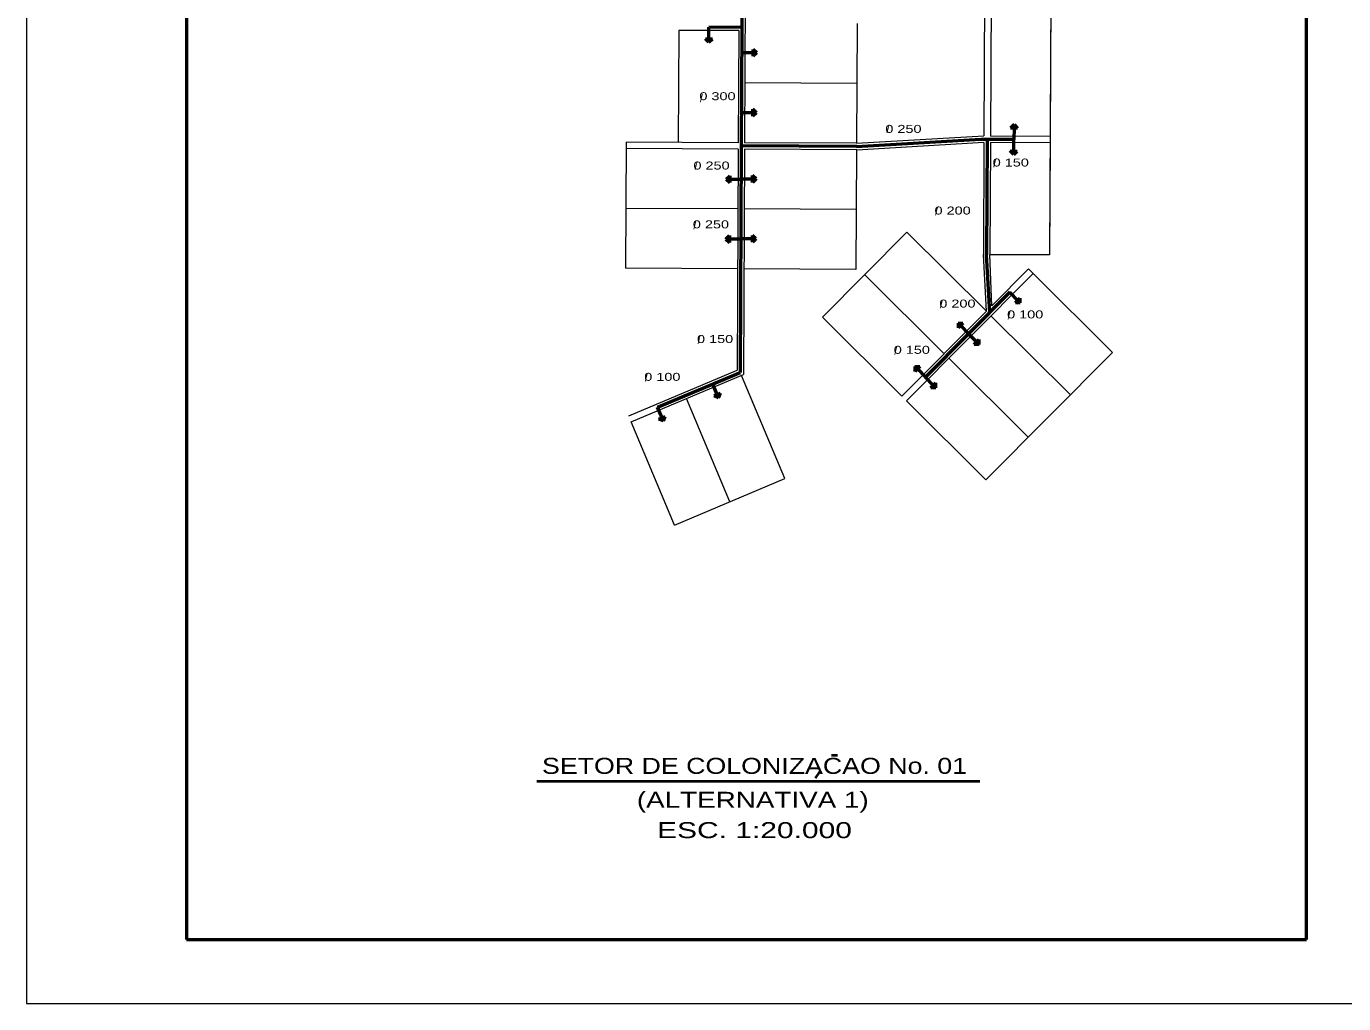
# Model space of a CAD drawing. Extents: x 312964 to 351929, y 9004151 to 9034973.
# Drawn here: x 343351 to 347467, y 9013061 to 9016114 of the extents above; entities that cross this region are included whole.
import ezdxf
from ezdxf.enums import TextEntityAlignment as Align

# ---------------------------------------------------------------- set-up
doc = ezdxf.new("R2010")
doc.units = 0
doc.header["$LTSCALE"] = 10
doc.layers.add('1', color=7, linetype='Continuous', lineweight=13)
doc.layers.add('2', color=7, linetype='Continuous', lineweight=53)

msp = doc.modelspace()

# ---------------------------------------------------------------- linework, layer by layer
at = {"layer": '1', "lineweight": 53}
for p, q in [((343850.92, 9018801.07), (343850.92, 9013261.07)), ((347350.92, 9013261.07), (347350.92, 9018801.07)), ((343850.92, 9013261.07), (347350.92, 9013261.07))]:
    msp.add_line(p, q, dxfattribs=at)
at = {"layer": '1', "lineweight": 40}
for p, q in [((345866.77, 9013837.69), (345885.06, 9013837.69)), ((344945.51, 9013756.03), (346329.85, 9013756.03)), ((345828.79, 9013785.6), (345816.12, 9013765.89))]:
    msp.add_line(p, q, dxfattribs=at)
at = {"layer": '1'}
msp.add_lwpolyline([(343350.92, 9019001.07), (343350.92, 9013061.07), (347550.92, 9013061.07), (347550.92, 9019001.07)], close=True, dxfattribs=at)
at = {"layer": '2', "lineweight": 13}
for p, q in [((345598.53, 9016474.5), (345594.98, 9015750.51)), ((346346.52, 9016470.83), (346343.09, 9015772.11)), ((346366.52, 9016470.73), (346363.09, 9015770.74)), ((346553.51, 9016469.82), (346548.27, 9015399.83)), ((346553.51, 9016469.82), (346550.08, 9015769.83)), ((345389.69, 9016101.52), (345387.98, 9015751.52)), ((345576.69, 9016100.6), (345389.69, 9016101.52)), ((345576.69, 9016100.6), (345574.98, 9015750.61)), ((345946.81, 9016122.79), (345944.97, 9015748.79)), ((345945.89, 9015935.79), (345595.89, 9015937.51)), ((345944.97, 9015748.79), (346343.09, 9015772.11)), ((346550.08, 9015769.83), (346363.09, 9015770.74)), ((345224.98, 9015752.32), (345223.05, 9015358.33)), ((345574.88, 9015730.61), (345224.88, 9015732.32)), ((345574.98, 9015750.61), (345224.98, 9015752.32)), ((345574.88, 9015730.61), (345571.49, 9015039.53)), ((345594.88, 9015730.51), (345591.43, 9015026.21)), ((345945.51, 9015728.79), (345594.88, 9015730.51)), ((345944.97, 9015748.79), (345594.98, 9015750.51)), ((345944.87, 9015728.79), (345943.04, 9015354.8)), ((345945.51, 9015728.79), (346342.99, 9015752.07)), ((346342.99, 9015750.8), (346341.27, 9015400.85)), ((346362.99, 9015750.74), (346361.27, 9015400.75)), ((346549.99, 9015749.83), (346362.99, 9015750.74)), ((346549.99, 9015749.83), (346548.27, 9015399.83)), ((345573.96, 9015543.61), (345223.97, 9015545.32)), ((345943.96, 9015541.79), (345593.96, 9015543.51)), ((346102.48, 9015470.74), (345838.75, 9015205.56)), ((346350.65, 9015223.93), (346102.48, 9015470.74)), ((346350.65, 9015223.93), (346341.27, 9015400.85)), ((346548.27, 9015399.83), (346361.27, 9015400.75)), ((346367.78, 9015241.15), (346361.27, 9015400.75)), ((345573.05, 9015356.61), (345223.05, 9015358.33)), ((345943.04, 9015354.8), (345593.05, 9015356.51)), ((346218.79, 9015091.34), (345970.62, 9015338.15)), ((346496.7, 9015342.42), (346101.1, 9014944.65)), ((346482.52, 9015356.53), (346367.78, 9015241.15)), ((346482.52, 9015356.53), (346496.7, 9015342.42)), ((346496.7, 9015342.42), (346744.86, 9015095.62)), ((346086.92, 9014958.75), (345838.75, 9015205.56)), ((346350.65, 9015223.93), (346086.92, 9014958.75)), ((346364.83, 9015209.83), (346613, 9014963.03)), ((346232.97, 9015077.24), (346481.13, 9014830.43)), ((346744.86, 9015095.62), (346349.27, 9014697.84)), ((345233.21, 9014897.37), (345571.49, 9015039.53)), ((345240.96, 9014878.94), (345591.43, 9015026.21)), ((345721.35, 9014701.16), (345585.75, 9015023.83)), ((345548.95, 9014628.72), (345413.35, 9014951.38)), ((346101.1, 9014944.65), (346349.27, 9014697.84)), ((345376.55, 9014556.27), (345240.96, 9014878.94)), ((345376.55, 9014556.27), (345721.35, 9014701.16))]:
    msp.add_line(p, q, dxfattribs=at)
at = {"layer": '2'}
for p, q in [((345586.74, 9016110.55), (345483.24, 9016111.06)), ((345483.29, 9016075.21), (345483.24, 9016111.06)), ((345472.77, 9016075.2), (345494.33, 9016075.23)), ((345483.56, 9016064.43), (345472.77, 9016075.2)), ((345483.56, 9016064.43), (345494.33, 9016075.23)), ((345622.2, 9016031.1), (345586.35, 9016031.05)), ((345622.21, 9016020.58), (345622.19, 9016042.14)), ((345632.98, 9016031.37), (345622.19, 9016042.14)), ((345632.98, 9016031.37), (345622.21, 9016020.58)), ((345621.3, 9015833.58), (345621.27, 9015855.14)), ((345632.06, 9015844.38), (345621.27, 9015855.14)), ((345621.28, 9015844.1), (345585.44, 9015844.06)), ((345632.06, 9015844.38), (345621.3, 9015833.58)), ((346437.1, 9015807.01), (346426.13, 9015796.42)), ((346447.69, 9015796.04), (346426.13, 9015796.42)), ((346437.17, 9015796.23), (346436.54, 9015760.38)), ((346437.1, 9015807.01), (346447.69, 9015796.04)), ((345945.56, 9015738.79), (345584.93, 9015740.56)), ((345944.92, 9015738.77), (346333.04, 9015761.5)), ((346436.54, 9015760.38), (346333.04, 9015760.89)), ((346353.04, 9015761.41), (346351.27, 9015400.8)), ((346435.9, 9015724.54), (346436.54, 9015760.38)), ((346425.38, 9015724.73), (346446.94, 9015724.34)), ((346435.97, 9015713.76), (346425.38, 9015724.73)), ((346435.97, 9015713.76), (346446.94, 9015724.34)), ((345537.79, 9015636.74), (345548.56, 9015647.53)), ((345548.56, 9015647.53), (345548.59, 9015625.97)), ((345620.28, 9015626.59), (345620.25, 9015648.14)), ((345631.05, 9015637.38), (345620.25, 9015648.14)), ((345537.79, 9015636.74), (345548.59, 9015625.97)), ((345548.57, 9015637.01), (345584.42, 9015637.06)), ((345620.27, 9015637.11), (345584.42, 9015637.06)), ((345631.05, 9015637.38), (345620.28, 9015626.59)), ((345536.88, 9015449.74), (345547.64, 9015460.53)), ((345536.88, 9015449.74), (345547.67, 9015438.97)), ((345547.64, 9015460.53), (345547.67, 9015438.97)), ((345547.66, 9015450.01), (345583.5, 9015450.06)), ((345619.35, 9015450.11), (345583.5, 9015450.06)), ((345619.37, 9015439.59), (345619.34, 9015461.15)), ((345630.13, 9015450.38), (345619.34, 9015461.15)), ((345630.13, 9015450.38), (345619.37, 9015439.59)), ((346361.36, 9015220.52), (346351.27, 9015400.8)), ((346423.67, 9015283.18), (346159.94, 9015017.99)), ((346448.64, 9015257.45), (346423.67, 9015283.18)), ((346441.09, 9015250.13), (346456.56, 9015265.14)), ((346456.33, 9015249.9), (346441.09, 9015250.13)), ((346456.33, 9015249.9), (346456.56, 9015265.14)), ((346262.29, 9015187.02), (346262.06, 9015171.78)), ((346277.53, 9015186.79), (346262.06, 9015171.78)), ((346262.29, 9015187.02), (346277.53, 9015186.79)), ((346269.98, 9015179.47), (346294.95, 9015153.74)), ((346319.91, 9015128.02), (346294.95, 9015153.74)), ((346312.36, 9015120.69), (346327.84, 9015135.71)), ((346327.61, 9015120.46), (346312.36, 9015120.69)), ((346327.61, 9015120.46), (346327.84, 9015135.71)), ((345323.28, 9014924.38), (345581.46, 9015032.87)), ((346127.28, 9015051.27), (346127.06, 9015036.03)), ((346142.53, 9015051.05), (346127.06, 9015036.03)), ((346127.28, 9015051.27), (346142.53, 9015051.05)), ((346134.98, 9015043.72), (346159.94, 9015017.99)), ((345509.54, 9014963.77), (345495.61, 9014996.8)), ((346184.91, 9014992.27), (346159.94, 9015017.99)), ((346177.36, 9014984.94), (346192.83, 9014999.96)), ((346192.6, 9014984.71), (346192.83, 9014999.96)), ((345499.85, 9014959.68), (345519.71, 9014968.06)), ((345513.97, 9014953.93), (345499.85, 9014959.68)), ((345513.97, 9014953.93), (345519.71, 9014968.06)), ((346192.6, 9014984.71), (346177.36, 9014984.94)), ((345337.21, 9014891.35), (345323.28, 9014924.38)), ((345327.52, 9014887.26), (345347.38, 9014895.64)), ((345341.64, 9014881.52), (345327.52, 9014887.26)), ((345341.64, 9014881.52), (345347.38, 9014895.64))]:
    msp.add_line(p, q, dxfattribs=at)
msp.add_lwpolyline([(345588.57, 9016484.55), (345584.93, 9015740.56), (345581.46, 9015032.87)], dxfattribs=at)

# ---------------------------------------------------------------- texts
at = {"layer": '1'}
for s, width, p in [('SETOR DE COLONIZACAO No. 01', 1.25, (345626.2, 9013778.9)), ('(ALTERNATIVA 1)', 1.3, (345620.76, 9013672.79)), ('ESC. 1:20.000', 1.4, (345626.02, 9013578.14))]:
    msp.add_text(s, height=50, dxfattribs=dict(at, width=width)).set_placement(p, align=Align.CENTER)
at = {"layer": '2'}
for p in [(345460.3, 9015877.37), (346043.24, 9015780.81), (345443.58, 9015666.41), (346376.79, 9015673.93), (346195.01, 9015523.89), (345439.83, 9015480.74), (346210.01, 9015233.2), (346421.76, 9015199.44), (345452.93, 9015122.54), (346067.59, 9015088.79), (345288.02, 9015004.39)]:
    msp.add_text('/', height=25, dxfattribs=at).set_placement(p, align=Align.CENTER)
at = {"layer": '2', "width": 1.35}
for s, p in [('0 300', (345510.41, 9015883.39)), ('0 250', (346091.47, 9015781.2)), ('0 250', (345491.81, 9015666.8)), ('0 150', (346426.89, 9015676.2)), ('0 200', (346245.12, 9015526.16)), ('0 250', (345489.93, 9015483.01)), ('0 200', (346260.11, 9015235.47)), ('0 100', (346471.87, 9015201.71)), ('0 150', (345503.04, 9015124.81)), ('0 150', (346117.69, 9015091.05)), ('0 100', (345338.13, 9015006.66))]:
    msp.add_text(s, height=25, dxfattribs=at).set_placement(p, align=Align.CENTER)

doc.saveas('drawing.dxf')
